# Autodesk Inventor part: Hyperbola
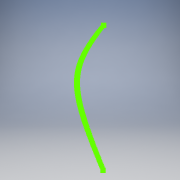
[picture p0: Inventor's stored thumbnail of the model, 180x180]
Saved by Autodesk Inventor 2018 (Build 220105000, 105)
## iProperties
Created: 2008-02
Part Number: Hyperbola
Document SubType Name: Modeling
Designer: Autodesk, Inc.
Density: 1 g/cm^3
Material: Generic
Appearance: Default
Author: Autodesk, Inc.
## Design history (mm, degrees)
sketch "Sketch1"
  geometry: 300 further points
  constraints: 300 other
